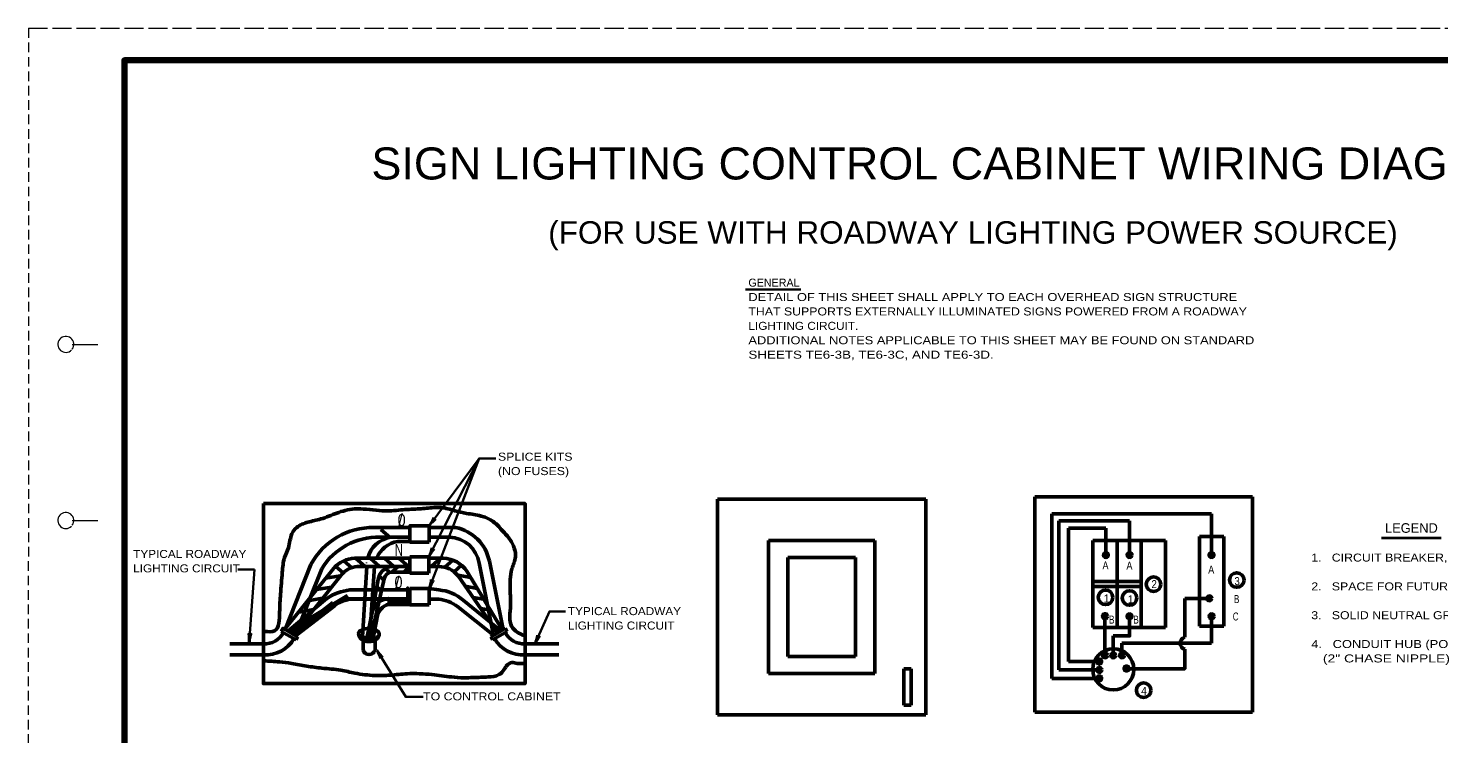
# Model space of a CAD drawing. Extents: x -1 to 679, y -1 to 440.
# Drawn here: x -1.1 to 439.6, y 219.3 to 439.7 of the extents above; entities that cross this region are included whole.
import ezdxf

# ---------------------------------------------------------------- set-up
doc = ezdxf.new("R2010")
doc.units = 0
doc.linetypes.add('LONG_DASHED', pattern=[7.5, 6, -1.5])
doc.linetypes.add('MEDIUM_DASHED', pattern=[4.5, 3, -1.5])
doc.layers.add('1', color=7, linetype='Continuous', lineweight=53)
doc.layers.add('61', color=7, linetype='Continuous', lineweight=35)

msp = doc.modelspace()

# ---------------------------------------------------------------- hatches: boundary and pattern name
at = {"layer": '1'}
for points in [[(336.338, 275.174, 1), (334.826, 275.174, 1)], [(343.736, 275.159, 1), (342.224, 275.159, 1)], [(369.345, 275.151, 1), (367.832, 275.151, 1)], [(368.633, 261.612, 1), (367.12, 261.612, 1)], [(336.082, 256.06, 1), (334.569, 256.06, 1)], [(343.7, 255.996, 1), (342.188, 255.996, 1)], [(369.356, 256.028, 1), (367.844, 256.028, 1)], [(334.258, 241.902, 1), (332.745, 241.902, 1)], [(336.044, 243.83, 1), (334.532, 243.83, 1)], [(338.634, 243.83, 1), (337.121, 243.83, 1)], [(341.384, 243.83, 1), (339.871, 243.83, 1)], [(334.278, 239.272, 1), (332.765, 239.272, 1)], [(342.768, 239.713, 1), (341.256, 239.713, 1)], [(334.258, 236.661, 1), (332.745, 236.661, 1)]]:
    msp.add_hatch(color=256, dxfattribs=at).paths.add_polyline_path(points)

# ---------------------------------------------------------------- linework, layer by layer
at = {"layer": '1', "linetype": 'MEDIUM_DASHED', "lineweight": 13}
msp.add_line((-1.032, 439.694), (-1.093, -0.346), dxfattribs=at)
at = {"layer": '1', "lineweight": 35}
for p, q in [((223.009, 358.139), (240.27, 358.139)), ((139.78, 305.31), (124.158, 264.666)), ((139.78, 305.31), (145.009, 305.31)), ((69.554, 270.675), (64.411, 270.679)), ((67.948, 247.858), (69.554, 270.675))]:
    msp.add_line(p, q, dxfattribs=at)
at = {"layer": '1'}
for p, q in [((214.263, 292.567), (214.263, 225.26)), ((214.263, 292.567), (279.301, 292.567)), ((279.301, 292.567), (279.301, 225.26)), ((313.352, 293.354), (313.352, 226.048)), ((313.352, 293.354), (381.414, 293.354)), ((381.414, 293.354), (381.414, 226.048)), ((318.645, 288.06), (318.645, 236.635)), ((318.645, 288.06), (368.591, 288.06)), ((368.591, 288.06), (368.591, 274.448)), ((106.902, 283.742), (118.152, 283.742)), ((112.08, 280.543), (109.114, 283.171)), ((118.152, 284.278), (124.152, 284.278)), ((118.152, 284.278), (118.152, 279.179)), ((118.152, 284.278), (118.152, 279.179)), ((118.152, 284.278), (118.152, 279.179)), ((124.152, 284.278), (124.152, 279.179)), ((124.152, 283.742), (132.402, 283.742)), ((320.914, 285.791), (320.914, 239.295)), ((320.914, 285.791), (342.966, 285.791)), ((323.939, 283.523), (323.939, 241.929)), ((323.939, 283.523), (335.55, 283.523)), ((335.55, 283.523), (335.55, 274.448)), ((342.966, 285.791), (342.966, 274.448)), ((118.152, 280.742), (108.777, 280.742)), ((108.777, 280.742), (118.152, 280.742)), ((108.777, 280.742), (118.152, 280.742)), ((118.36, 279.373), (114.351, 279.373)), ((118.152, 279.179), (124.152, 279.179)), ((230.145, 279.71), (230.145, 238.117)), ((230.145, 279.71), (263.42, 279.71)), ((263.42, 279.71), (263.42, 238.117)), ((331.502, 279.741), (331.502, 252.516)), ((331.502, 279.741), (354.189, 279.741)), ((339.064, 279.741), (339.064, 252.516)), ((346.627, 279.741), (346.627, 252.516)), ((354.189, 279.741), (354.189, 252.516)), ((364.81, 252.917), (364.81, 280.899)), ((364.81, 280.899), (372.372, 280.899)), ((372.372, 252.917), (372.372, 280.899)), ((100.018, 271.19), (97.56, 273.368)), ((118.152, 274.177), (100.902, 274.177)), ((104.123, 271.561), (101.156, 274.189)), ((108.647, 271.561), (105.694, 274.177)), ((113.171, 271.561), (110.218, 274.177)), ((117.695, 271.561), (114.742, 274.177)), ((118.095, 274.63), (124.095, 274.63)), ((118.095, 274.63), (118.095, 269.531)), ((124.095, 274.63), (124.095, 269.531)), ((128.652, 274.177), (124.095, 274.177)), ((124.778, 271.561), (127.731, 274.177)), ((129.043, 271.331), (131.549, 273.551)), ((142.991, 273.229), (147.258, 251.858)), ((236.195, 274.417), (236.195, 243.41)), ((236.195, 274.417), (257.37, 274.417)), ((257.37, 274.417), (257.37, 243.41)), ((94.349, 271.077), (79.122, 251.948)), ((79.157, 251.928), (87.226, 272.212)), ((97.062, 269.429), (81.888, 250.367)), ((90.586, 270.875), (82.328, 250.116)), ((97.257, 269.628), (95.036, 271.596)), ((102.402, 271.561), (118.095, 271.561)), ((102.402, 271.561), (118.095, 271.561)), ((103.324, 249.592), (104.706, 271.561)), ((111.843, 269.705), (110.483, 270.91)), ((114.448, 271.561), (112.501, 269.836)), ((112.549, 269.836), (118.095, 269.836)), ((118.167, 271.561), (116.219, 269.836)), ((118.095, 269.531), (124.095, 269.531)), ((127.152, 271.561), (124.095, 271.561)), ((131.951, 269.9), (134.274, 271.957)), ((137.168, 268.141), (133.073, 268.839)), ((135.962, 270.149), (147.028, 251.726)), ((144.248, 250.137), (139.766, 272.585)), ((89.013, 264.372), (93.667, 265.165)), ((91.815, 267.893), (96.469, 268.685)), ((110.107, 267.711), (105.816, 248.852)), ((108.265, 267.468), (105.947, 254.983)), ((109.258, 263.979), (107.849, 265.227)), ((110.016, 267.315), (108.553, 268.612)), ((118.158, 264.666), (124.158, 264.666)), ((118.158, 264.666), (118.158, 259.567)), ((118.158, 264.666), (118.158, 259.567)), ((124.158, 264.666), (124.158, 259.567)), ((133.208, 268.643), (145.495, 250.85)), ((139.204, 264.751), (135.455, 265.39)), ((331.502, 266.885), (346.627, 266.885)), ((346.627, 265.373), (331.502, 265.373)), ((80.054, 251.415), (92.218, 261.571)), ((80.871, 251.746), (98.66, 262.548)), ((80.911, 251.679), (98.7, 262.481)), ((80.948, 251.619), (98.737, 262.421)), ((81.153, 251.282), (98.942, 262.084)), ((82.058, 251.007), (94.056, 260.297)), ((82.127, 250.919), (94.125, 260.209)), ((82.226, 250.791), (94.224, 260.081)), ((82.26, 250.747), (94.258, 260.037)), ((82.269, 250.735), (94.267, 260.025)), ((82.269, 250.735), (94.267, 260.025)), ((86.21, 260.852), (90.865, 261.644)), ((99.402, 264.242), (118.158, 264.242)), ((118.158, 261.327), (99.402, 261.327)), ((118.158, 261.327), (99.402, 261.327)), ((118.158, 261.327), (99.402, 261.327)), ((118.158, 261.327), (99.402, 261.327)), ((107.68, 259.806), (106.961, 260.443)), ((111.157, 261.235), (118.152, 261.266)), ((111.157, 261.235), (118.152, 261.266)), ((111.157, 261.178), (118.152, 261.209)), ((111.157, 261.122), (118.153, 261.152)), ((111.157, 261.122), (118.153, 261.152)), ((111.157, 261.107), (118.153, 261.138)), ((111.157, 261.107), (118.153, 261.138)), ((111.157, 261.079), (118.153, 261.109)), ((111.157, 261.065), (118.153, 261.095)), ((111.157, 261.036), (118.153, 261.066)), ((111.158, 260.979), (118.153, 261.009)), ((111.158, 260.951), (118.153, 260.981)), ((111.158, 260.951), (118.153, 260.981)), ((111.158, 260.88), (118.154, 260.91)), ((111.158, 260.823), (118.154, 260.853)), ((111.159, 260.78), (118.154, 260.81)), ((111.159, 260.78), (118.154, 260.81)), ((111.159, 260.766), (118.154, 260.796)), ((111.159, 260.752), (118.154, 260.782)), ((111.159, 260.709), (118.154, 260.739)), ((111.159, 260.652), (118.155, 260.682)), ((111.159, 260.637), (118.155, 260.668)), ((111.159, 260.623), (118.155, 260.654)), ((111.159, 260.623), (118.155, 260.654)), ((111.159, 260.623), (118.155, 260.654)), ((111.159, 260.58), (118.155, 260.611)), ((111.16, 260.538), (118.155, 260.568)), ((111.16, 260.524), (118.155, 260.554)), ((111.16, 260.481), (118.155, 260.511)), ((111.16, 260.481), (118.155, 260.511)), ((111.16, 260.452), (118.156, 260.483)), ((111.16, 260.396), (118.156, 260.426)), ((111.16, 260.395), (118.156, 260.426)), ((111.16, 260.381), (118.156, 260.412)), ((111.16, 260.325), (118.156, 260.355)), ((111.161, 260.281), (118.156, 260.312)), ((111.161, 260.267), (118.156, 260.298)), ((111.161, 260.239), (118.156, 260.27)), ((111.161, 260.168), (118.157, 260.198)), ((111.161, 260.168), (118.157, 260.198)), ((111.161, 260.14), (118.157, 260.17)), ((111.161, 260.139), (118.157, 260.169)), ((111.161, 260.111), (118.157, 260.141)), ((111.162, 260.068), (118.157, 260.098)), ((111.162, 260.025), (118.157, 260.055)), ((111.162, 260.011), (118.157, 260.041)), ((111.162, 259.997), (118.158, 260.028)), ((111.162, 259.983), (118.158, 260.013)), ((111.162, 259.968), (118.158, 259.999)), ((117.358, 260.02), (112.14, 259.998)), ((112.14, 259.998), (117.358, 260.02)), ((112.14, 259.998), (117.358, 260.02)), ((117.456, 261.794), (117.456, 261.979)), ((117.456, 259.717), (117.456, 261.327)), ((127.152, 261.327), (124.158, 261.327)), ((134.757, 261.032), (146.532, 251.442)), ((141.24, 261.361), (137.836, 261.941)), ((360.239, 249.491), (360.239, 261.591)), ((360.239, 261.591), (368.591, 261.591)), ((81.613, 250.524), (93.661, 258.781)), ((82.387, 250.582), (94.385, 259.872)), ((82.396, 250.571), (94.394, 259.861)), ((82.415, 250.546), (94.413, 259.836)), ((82.471, 250.474), (94.469, 259.764)), ((82.471, 250.474), (94.469, 259.764)), ((82.551, 250.371), (94.549, 259.661)), ((82.579, 250.335), (94.577, 259.625)), ((82.635, 250.262), (94.633, 259.552)), ((82.654, 250.238), (94.652, 259.528)), ((82.669, 250.218), (94.667, 259.508)), ((82.754, 250.11), (94.752, 259.4)), ((83.408, 257.332), (88.062, 258.124)), ((104.677, 249.091), (106.508, 257.752)), ((111.162, 259.955), (118.158, 259.985)), ((111.162, 259.912), (118.158, 259.942)), ((111.162, 259.883), (118.158, 259.914)), ((111.162, 259.869), (118.158, 259.9)), ((111.163, 259.826), (118.158, 259.857)), ((111.163, 259.784), (118.158, 259.814)), ((111.163, 259.769), (118.159, 259.8)), ((111.163, 259.715), (118.159, 259.745)), ((118.158, 259.567), (124.158, 259.567)), ((144.248, 250.137), (133.012, 259.09)), ((143.276, 257.971), (140.218, 258.492)), ((335.278, 256.698), (335.278, 243.086)), ((368.591, 247.623), (368.591, 256.698)), ((78.535, 252.283), (77.977, 251.306)), ((78.535, 252.283), (77.977, 251.306)), ((77.977, 251.306), (82.576, 248.678)), ((78.535, 252.283), (83.134, 249.655)), ((78.535, 252.283), (83.134, 249.655)), ((148.003, 252.283), (143.404, 249.655)), ((148.003, 252.283), (143.404, 249.655)), ((148.003, 252.283), (143.404, 249.655)), ((148.561, 251.306), (143.962, 248.678)), ((148.003, 252.283), (148.561, 251.306)), ((354.189, 252.516), (331.502, 252.516)), ((364.81, 252.917), (372.372, 252.917)), ((72.402, 247.367), (61.902, 247.367)), ((83.134, 249.655), (82.576, 248.678)), ((103.503, 245.549), (103.503, 248.549)), ((107.253, 245.549), (107.253, 248.549)), ((143.404, 249.655), (143.962, 248.678)), ((154.136, 247.367), (164.636, 247.367)), ((337.878, 249.892), (337.878, 243.086)), ((340.61, 247.623), (368.591, 247.623)), ((340.61, 247.623), (340.61, 243.086)), ((72.402, 243.992), (61.902, 243.992)), ((154.136, 243.992), (164.636, 243.992)), ((236.195, 243.41), (257.37, 243.41)), ((230.145, 238.117), (263.42, 238.117)), ((272.495, 239.629), (272.495, 228.285)), ((272.495, 239.629), (274.763, 239.629)), ((274.763, 239.629), (274.763, 228.285)), ((320.914, 239.295), (334.246, 239.295)), ((323.939, 241.929), (334.246, 241.929)), ((72.402, 234.992), (154.152, 234.992)), ((318.645, 236.635), (334.246, 236.635)), ((214.263, 225.26), (279.301, 225.26)), ((272.495, 228.285), (274.763, 228.285)), ((313.352, 226.048), (381.414, 226.048))]:
    msp.add_line(p, q, dxfattribs=at)
at = {"layer": '1', "lineweight": 40}
msp.add_line((421.661, 280.528), (440.27, 280.528), dxfattribs=at)
at = {"layer": '1', "lineweight": 35}
for points in [[(124.152, 284.278), (139.78, 305.31), (124.095, 274.63)], [(157.197, 247.329), (161.745, 257.545), (166.808, 257.545)], [(107.832, 245.458), (116.839, 230.855), (122.286, 230.855)]]:
    msp.add_lwpolyline(points, dxfattribs=at)
at = {"layer": '1'}
msp.add_lwpolyline([(72.402, 291.242), (154.152, 291.242), (154.152, 234.992), (72.402, 234.992)], close=True, dxfattribs=at)
for points in [[(118.152, 279.179), (118.152, 284.278), (118.152, 279.179)], [(130.527, 280.742), (124.152, 280.742), (124.152, 283.742)], [(100.902, 274.177), (118.152, 274.177), (105.009, 274.177)], [(107.048, 271.561), (105.529, 248.94), (103.324, 249.592)], [(117.456, 259.717), (117.456, 264.817), (117.456, 259.717)], [(124.158, 259.567), (124.158, 264.666), (127.152, 264.242)], [(117.456, 261.477), (98.7, 261.477), (117.456, 261.477)], [(93.661, 258.781), (81.613, 250.524), (80.054, 251.415)], [(108.011, 256.298), (106.644, 249.172), (104.677, 249.091)], [(337.878, 249.892), (342.976, 249.892), (342.976, 256.698)], [(83.134, 249.655), (78.535, 252.283), (79.157, 251.928)], [(341.333, 239.66), (360.239, 239.66), (360.239, 245.71)]]:
    msp.add_lwpolyline(points, dxfattribs=at)
for centre, radius in [((335.582, 275.174), 0.756), ((342.98, 275.159), 0.756), ((368.588, 275.151), 0.756), ((376.468, 267.336), 2.269), ((350.475, 266.036), 2.269), ((335.478, 261.936), 2.269), ((342.977, 261.736), 2.269), ((367.877, 261.612), 0.756), ((335.326, 256.06), 0.756), ((342.944, 255.996), 0.756), ((368.6, 256.028), 0.756), ((337.878, 239.434), 6.428), ((333.501, 241.902), 0.756), ((335.288, 243.83), 0.756), ((337.877, 243.83), 0.756), ((340.627, 243.83), 0.756), ((333.522, 239.272), 0.756), ((342.012, 239.713), 0.756), ((333.501, 236.661), 0.756), ((347.376, 232.934), 2.269)]:
    msp.add_circle(centre, radius, dxfattribs=at)
for centre, radius, start, end in [((106.557, 261.776), 21.969, 89.10191, 151.63788), ((129.772, 270.504), 13.497, 11.64983, 78.7649), ((108.336, 259.853), 20.894, 88.79119, 148.16004), ((113.516, 272.08), 8.762, 99.33482, 166.15506), ((115.772, 270.727), 8.762, 99.33482, 156.80988), ((130.227, 271.091), 9.655, 8.89802, 88.21923), ((101.483, 264.475), 9.72, 93.43035, 137.21811), ((128.07, 264.475), 9.72, 35.7187, 86.56965), ((102.38, 263.861), 7.7, 89.83779, 133.68639), ((113.516, 272.08), 8.762, 175.66188, 175.86711), ((112.912, 266.908), 4.681, 99.31769, 173.13631), ((112.663, 267.238), 2.6, 92.52451, 169.51096), ((127.174, 263.861), 7.7, 38.39054, 90.16221), ((101.128, 248.603), 15.734, 96.30064, 124.49318), ((102.196, 244.464), 17.093, 99.4097, 120.64994), ((100.954, 250.081), 11.352, 97.85747, 129.97371), ((111.63, 256.189), 5.356, 80.69802, 163.0273), ((113.134, 254.735), 5.356, 100.69421, 163.0273), ((113.134, 254.735), 5.356, 100.69421, 163.0273), ((113.134, 254.735), 5.356, 100.69421, 163.0273), ((126.29, 251.587), 12.684, 48.12198, 86.10351), ((125.878, 249.192), 12.201, 54.21547, 84.00793), ((72.587, 254.262), 6.897, 268.46061, 331.14947), ((73.14, 254.096), 10.131, 265.82241, 330.12509), ((153.398, 254.096), 10.131, 209.87491, 274.17759), ((153.951, 254.262), 6.897, 208.85053, 271.53939), ((360.708, 247.601), 1.948, 103.91543, 256.08457), ((105.378, 246.038), 1.938, 194.60928, 345.39072)]:
    msp.add_arc(centre, radius, start, end, dxfattribs=at)
at = {"layer": '1', "lineweight": 40}
for centre, major_axis, ratio, start_param, end_param in [((124.581, 285.319), (-0.94, -1.526), 0.122415, 0.8963533, 3.1415927), ((124.99, 285.051), (-1.189, -1.305), 0.07063, 3.1407148, 5.41811), ((124.346, 275.728), (-0.674, -1.661), 0.122415, 0.8963533, 3.1415927), ((124.794, 275.532), (-0.956, -1.484), 0.07063, 3.1407148, 5.41811), ((124.291, 265.784), (-0.495, -1.723), 0.122415, 0.8963533, 3.1415927), ((124.757, 265.636), (0.794, 1.576), 0.07063, 6.2823074, 8.5597026), ((67.749, 248.966), (0.03, -1.792), 0.122415, 0.8963533, 3.1415927), ((68.238, 248.961), (0.299, 1.74), 0.07063, 6.2823074, 8.5597026), ((157.388, 248.438), (-0.584, -1.695), 0.122415, 0.8963533, 3.1415927), ((157.846, 248.267), (0.875, 1.533), 0.07063, 6.2823074, 8.5597026), ((108.24, 244.394), (0.772, -1.587), 0.07063, 6.2823074, 8.5597026), ((108.24, 244.394), (0.772, -1.587), 0.07063, 6.2823074, 8.5597026), ((108.64, 244.675), (-1.07, 1.438), 0.122415, 0.8963533, 3.1415927), ((108.64, 244.675), (-1.07, 1.438), 0.122415, 0.8963533, 3.1415927)]:
    msp.add_ellipse(centre, major_axis=major_axis, ratio=ratio, start_param=start_param, end_param=end_param, dxfattribs=at)
at = {"layer": '1'}
msp.add_ellipse((105.357, 250.545), major_axis=(3.232, -0.12), ratio=0.505045, dxfattribs=at)
msp.add_ellipse((105.357, 250.545), major_axis=(3.232, -0.12), ratio=0.757256, start_param=3.1415927, end_param=6.2831853, dxfattribs=at)
for points in [[(72.674, 251.312), (75.889, 251.496), (77.45, 257.285), (77.726, 262.982), (78.277, 269.781), (79.012, 274.376), (80.206, 277.408), (81.308, 281.819), (82.778, 283.748), (86.269, 285.402), (90.31, 286.413), (95.271, 288.251), (97.935, 289.078), (100.874, 289.537), (104.64, 289.445), (112.448, 288.986), (115.296, 289.261), (120.531, 289.537), (125.032, 289.905), (127.88, 289.996), (132.197, 288.986), (135.872, 288.159), (140.373, 287.332), (143.679, 285.953), (147.078, 282.737), (149.466, 279.889), (151.12, 274.559), (150.017, 270.792), (149.466, 264.268), (149.558, 261.879), (149.558, 258.571), (149.374, 254.988), (150.293, 252.323), (152.222, 250.761), (154.335, 249.842)], [(72.582, 242.123), (77.359, 241.756), (81.217, 241.296), (85.901, 240.469), (90.678, 239.826), (96.557, 239.183), (100.966, 238.264), (107.212, 237.529), (111.989, 237.621), (117.316, 238.08), (125.032, 237.805), (131.187, 237.07), (134.953, 236.794), (137.984, 236.886), (142.577, 237.07), (145.976, 237.805), (147.537, 239.275), (148.272, 240.469), (150.017, 241.572), (151.671, 241.296), (153.967, 241.205), (154.203, 241.095)]]:
    msp.add_spline(points, degree=3, dxfattribs=at)
at = {"layer": '61', "linetype": 'LONG_DASHED', "lineweight": 13}
msp.add_line((-1.032, 439.694), (678.987, 439.694), dxfattribs=at)
at = {"layer": '61', "lineweight": 13}
for p, q in [((12.688, 340.934), (20.668, 340.954)), ((12.668, 285.934), (20.668, 285.934))]:
    msp.add_line(p, q, dxfattribs=at)
at = {"layer": '61', "lineweight": 158}
msp.add_lwpolyline([(668.007, 429.694), (28.967, 429.694), (28.967, 9.674)], dxfattribs=at)
at = {"layer": '61', "lineweight": 13}
for centre, end in [((10.665, 340.935), 316.23216), ((10.665, 285.935), 315.37577)]:
    msp.add_arc(centre, 2.5, 323.13009, end, dxfattribs=at)

# ---------------------------------------------------------------- texts
at = {"layer": '1'}
for s, height, width, p in [('SIGN LIGHTING CONTROL CABINET WIRING DIAGRAMS', 10, 1.05, (106.121, 392.453)), ('(FOR USE WITH ROADWAY LIGHTING POWER SOURCE)', 7, 1.05, (161.368, 372.412)), ('DETAIL OF THIS SHEET SHALL APPLY TO EACH OVERHEAD SIGN STRUCTURE', 2.5, 1.2, (223.9, 354.48)), ('THAT SUPPORTS EXTERNALLY ILLUMINATED SIGNS POWERED FROM A ROADWAY', 2.5, 1.15, (223.9, 349.98)), ('LIGHTING CIRCUIT.', 2.5, 1.1, (223.9, 345.48)), ('ADDITIONAL NOTES APPLICABLE TO THIS SHEET MAY BE FOUND ON STANDARD', 2.5, 1.2, (223.9, 340.98)), ('SHEETS TE6-3B, TE6-3C, AND TE6-3D.', 2.5, 1.25, (223.9, 336.48)), ('SPLICE KITS', 2.5, 1.15, (145.658, 304.622)), ('(NO FUSES)', 2.5, 1.15, (145.658, 300.122)), ('0', 3.75, 0.9, (114.315, 284.196)), ('N', 3.75, 0.7, (113.444, 274.823)), ('TYPICAL ROADWAY', 2.5, 1.1, (31.703, 274.238)), ('1.   CIRCUIT BREAKER, SEE NOTE 1.', 2.5, 1.15, (399.745, 273.107)), ('LIGHTING CIRCUIT', 2.5, 1.1, (31.703, 269.738)), ('A', 2.5, 0.85, (334.512, 270.658)), ('A', 2.5, 0.85, (341.983, 270.594)), ('A', 2.5, 0.85, (367.537, 269.336)), ('0', 3.75, 0.9, (113.335, 264.797)), ('2', 2.5, 0.9, (349.819, 264.808)), ('3', 2.5, 0.9, (375.74, 265.759)), ('2.   SPACE FOR FUTURE BREAKER', 2.5, 1.15, (399.745, 264.107)), ('B', 2.5, 0.75, (375.589, 260.154)), ('TYPICAL ROADWAY', 2.5, 1.1, (167.501, 256.382)), ('B', 2.5, 0.75, (336.572, 253.736)), ('B', 2.5, 0.75, (344.175, 253.736)), ('C', 2.5, 0.75, (375.21, 254.71)), ('3.   SOLID NEUTRAL GROUND BAR', 2.5, 1.15, (399.745, 255.107)), ('LIGHTING CIRCUIT', 2.5, 1.1, (167.501, 251.882)), ('4.   CONDUIT HUB (POLE TYPE)', 2.5, 1.2, (399.745, 246.107)), ('   (2" CHASE NIPPLE)', 2.5, 1.3, (399.745, 241.607)), ('4', 2.5, 0.95, (346.594, 231.466)), ('TO CONTROL CABINET', 2.5, 1.15, (122.286, 229.765))]:
    msp.add_text(s, height=height, dxfattribs=dict(at, width=width)).set_placement(p)
for s, height, p in [('GENERAL', 2.5, (223.9, 358.98)), ('/', 3.75, (114.533, 284.305)), ('LEGEND', 3, (422.779, 282.094)), ('/', 3.75, (113.553, 264.797)), ('1', 2.5, (334.882, 260.356)), ('1', 2.5, (342.392, 260.074))]:
    msp.add_text(s, height=height, dxfattribs=at).set_placement(p)

doc.saveas('drawing.dxf')
